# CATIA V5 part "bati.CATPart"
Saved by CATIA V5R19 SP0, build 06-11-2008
Part number: bati
Bounding box of the stored display mesh (mm): x -200 to 200, y -36 to 10, z -210 to 150
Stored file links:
  C:\Users\Alex\IFMA\2A\IAO\Modélisation\bati.CATPart
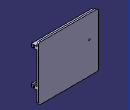
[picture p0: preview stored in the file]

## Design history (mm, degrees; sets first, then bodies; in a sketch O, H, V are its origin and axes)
Body1 (main body)
  Sketch1 on zx-plane, origin (0, 0, 0), H (-1, 0, 0), V (0, 0, 1)
    line L1 (-200, 150) -> (200, 150)
    line L2 (200, 150) -> (200, -210)
    line L3 (200, -210) -> (-200, -210)
    line L4 (-200, -210) -> (-200, 150)
    length L1 = 400
    distance L2 V = 200
    distance L1 H = 150
    length L2 = 360
    horizontal: L1 H, L3 H
    vertical: L2 V, L4 V
  Pad1: profile Sketch1, direction (0, 1, 0), length 10
  Sketch2 on face of Pad1 from Sketch1.L4, origin (200, 0, 0), H (0, 1, 0), V (0, 0, 1)
    point P1 (0, 125)
    line L1 (0, 125) -> (0, 105)
    line L2 (0, 105) -> (-16, 105)
    line L3 (-16, 105) -> (-16, 120)
    line L4 (-16, 120) -> (-26, 120)
    line L5 (-26, 120) -> (-26, 105)
    line L6 (-26, 105) -> (-36, 105)
    line L7 (-36, 105) -> (-36, 125)
    line L8 (-36, 125) -> (0, 125)
    length L4 = 10
    distance L1 L3 = 16
    distance L5 L7 = 10
    length L7 = 20
    distance L6 L4 = 15
    distance L2 L4 = 15
    distance L6 H = 105
    coincidence: P1 V
    vertical: L1 V, L3 V, L5 V, L7 V
    horizontal: L2 H, L4 H, L6 H, L8 H
  Pad2: profile Sketch2, direction (1, 0, 0), up to face of Pad1 from Sketch1.L2
  Mirror1: of Pad2, about xy-plane
  Sketch3 on start face of Pad1, origin (-137.8308, 0, 18.623), H (1, 0, 0), V (0, 0, 1)
    point P1 (-2.1692, -18.623)
    reference intersected line E1 through (0, -18.623) direction (-1, 0) from xy-plane
    reference projected line E2 (-62.1692, 106.377) -> (-62.1692, 131.377) from edge [start face of Pad1 | face of Pad1]
    distance P1 E2 = 60
    coincidence: E1 P1
  Hole1: placed by Sketch3, at (-140, 0, 0) direction (0, 1, 0), diameter 10, through (limit type 3)
  Fillet1: radius 15, on edge [face of Pad1 | face of Pad1 from Sketch1.L3]; edge [face of Pad1 from Sketch1.L3 | face of Pad1]; edge [face of Pad1 | face of Pad1 from Sketch1.L1]; edge [face of Pad1 from Sketch1.L1 | face of Pad1]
